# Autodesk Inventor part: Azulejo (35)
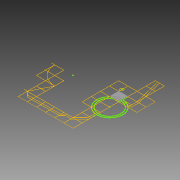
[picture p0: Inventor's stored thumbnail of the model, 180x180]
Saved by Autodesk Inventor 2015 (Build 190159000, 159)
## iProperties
Created: 2015-04
Part Number: Azulejo (35)
Material: Genérico
Document SubType Name: Modeling
Designer: Felipe
Density: 1 g/cm^3
Appearance: Padrão
Author: Felipe
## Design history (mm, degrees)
sketch "Sketch1"
  geometry: L1 (-1510, -7490)-(-1510, -6010); L2 (-3010, -1490)-(-3010, -10); L3 (-2990, 10)-(-1510, 10); L4 (-1510, -10)-(-2990, -10); L5 (-1510, -1490)-(-1510, -10); L6 (-1490, -10)-(-1490, -1490); L7 (-1490, -1490)-(-10, -1490); L8 (-10, -1510)-(-1490, -1510); L9 (-10, -2990)-(-10, -1510); L10 (-10, -5990)-(-10, -4510); L11 (-1490, -7490)-(-10, -7490); L12 (4490, -6010)-(3010, -6010); L13 (10, -1510)-(10, -2990); L14 (10, -3010)-(10, -4490); L15 (10, -4510)-(10, -5990); L16 (10, -5990)-(1490, -5990); L17 (1490, -6010)-(10, -6010); L18 (10, -7490)-(1490, -7490); L19 (1510, -5990)-(2990, -5990); L20 (2990, -6010)-(1510, -6010); L21 (1510, -7490)-(2990, -7490); L22 (4490, 1510)-(4490, 2990); L23 (4490, 10)-(4490, 1490); L24 (4490, -1490)-(4490, -10); L25 (4490, -2990)-(4490, -1510); L26 (3010, -5990)-(4490, -5990); L27 (3010, -7490)-(4490, -7490); L28 (4510, 3010)-(5990, 3010); L29 (5990, 2990)-(4510, 2990); L30 (4510, 2990)-(4510, 1510); L31 (4510, 1510)-(5990, 1510); L32 (5990, 1510)-(5990, 1740.185); L33 (5990, 1760.2)-(5990, 2259.8); L34 (5990, 2279.815)-(5990, 2990); L35 (5990, 1490)-(4510, 1490); L36 (4510, 1490)-(4510, 10); L37 (4510, 10)-(5990, 10); L38 (5990, 10)-(5990, 1490); L39 (5975.983, -10)-(4510, -10); L40 (4510, -10)-(4510, -1490); L41 (5990, -1510)-(5782.897, -1510); L42 (5782.897, -1510)-(5688.66, -1510); L43 (5668.66, -1510)-(5482.895, -1510); L44 (5482.895, -1510)-(5388.656, -1510); L45 (5368.656, -1510)-(4510, -1510); L46 (4510, -1510)-(4510, -2990); L47 (4510, -2990)-(5975.983, -2990); L48 (5990, -2975.728)-(5990, -2837.377); L49 (5990, -2837.377)-(5990, -2536.247); L50 (5990, -2500.476)-(5990, -2317.632); L51 (5990, -2317.632)-(5990, -1510); L52 (5990, -3010)-(4510, -3010); L53 (5990, -4490)-(5990, -3010); L54 (4510, -5990)-(5990, -5990); L55 (5990, -5990)-(5990, -4510); L56 (4510, -7490)-(5990, -7490); L57 (5990, -7490)-(5990, -6310); L58 (5990, -6290)-(5990, -6010); L59 (7490, 4510)-(7490, 5990); L60 (6010, 3010)-(7490, 3010); L61 (7490, 3010)-(7490, 4490); L62 (7490, 2990)-(6010, 2990); L63 (6010, 2990)-(6010, 2279.815); L64 (6010, 2259.8)-(6010, 1760.2)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; A1 r 250 centre (6000, 2010) between (5990, 2259.8) and (5990, 1760.2); A2 r 250 centre (6000, 2010) between (6010, 1760.2) and (6010, 2259.8); A3 r 270 centre (6000, 2010) between (5990, 2279.815) and (5990, 1740.185); A4 r 270 centre (6000, 2010) between (6010, 1740.185) and (6010, 2279.815); A5 r 3010.017 centre (0, 0) between (-1490, -2615.358) and (-346.554, -2990); A6 r 2990.017 centre (0, 0) between (-1490, -2592.316) and (-10, -2990); A7 r 3010.017 centre (0, 0) between (-2603.863, -1510) and (-1510, -2603.863); A8 r 2990.017 centre (0, 0) between (-2580.717, -1510) and (-1510, -2580.717); A9 r 3010.017 centre (0, 0) between (-2990, -346.554) and (-2615.358, -1490); A10 r 2990.017 centre (0, 0) between (-2990, -10) and (-2592.316, -1490); A11 r 2131.367 centre (7500, -1500) between (7490, 631.344) and (6010, 24.017); A12 r 2131.367 centre (7500, -1500) between (5975.983, -10) and (5368.656, -1490); A13 r 2131.367 centre (7500, -1500) between (5368.656, -1510) and (5975.983, -2990); A14 r 2131.367 centre (7500, -1500) between (6010, -3024.017) and (7190, -3608.703); A15 r 1831.367 centre (7500, -1500) between (7490.321, 331.342) and (6463.753, 10); A16 r 1831.367 centre (7500, -1500) between (7489.976, 331.34) and (6010, -435.196); A17 r 1831.367 centre (7500, -1500) between (5990, -463.753) and (5668.66, -1490); A18 r 1831.367 centre (7500, -1500) between (5668.66, -1510) and (5990, -2536.247); A19 r 1831.367 centre (7500, -1500) between (6010, -2564.804) and (6435.196, -2990); A20 r 1831.367 centre (7500, -1500) between (6463.753, -3010) and (7490, -3331.34); A21 r 2111.367 centre (7500, -1500) between (7490.389, 611.346) and (6024.272, 10); A22 r 2111.367 centre (7500, -1500) between (5990, -24.272) and (5388.656, -1490); A23 r 2111.367 centre (7500, -1500) between (5388.656, -1510) and (5990, -2975.728); A24 r 2111.367 centre (7500, -1500) between (6024.272, -3010) and (7210, -3591.357); A25 r 1811.367 centre (7499.986, -1499.91) between (7490.524, 311.432) and (6499.51, 10.09); A26 r 1811.367 centre (7500, -1500) between (6469.975, -10) and (6010, -469.975); A27 r 1811.367 centre (7500, -1500) between (5990, -499.524) and (5688.66, -1490); A28 r 1811.367 centre (7500, -1500) between (5688.66, -1510) and (5990, -2500.476); A29 r 1811.367 centre (7500, -1500) between (6010, -2530.025) and (6469.975, -2990); A30 r 1811.367 centre (7500, -1500) between (6499.524, -3010) and (7490, -3311.34); A31 r 449.871 centre (7499.449, -4060.672) between (7510, -4510.419) and (7521.546, -4510); A32 r 2111.367 centre (7500, -1500) between (7490.019, 611.344) and (7490.389, 611.346); A33 r 1831.367 centre (7500, -1500) between (7489.976, 331.34) and (7490.321, 331.342); A34 r 1811.367 centre (7499.986, -1499.91) between (7489.986, 311.429) and (7490.524, 311.432); 11 further points
  constraints: 714 end point, 75 point on circle, 34 centre point, 13 point on line, 3 concentric, 2 parallel, 2 perpendicular, 1 collinear, 1 horizontal, 1 vertical, 6 other
extrude "Extrusion1" new body sketch "Sketch1" distance "d0" = 60; taper "d1" = 0 deg
extrude "Extrusion2" new body sketch "Sketch1" distance "d2" = 60; taper "d3" = 0 deg
extrude "Extrusion3" new body sketch "Sketch1" distance "d4" = 60; taper "d5" = 0 deg
body "Solid1"
body "Solid2"
body "Solid3"
